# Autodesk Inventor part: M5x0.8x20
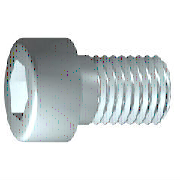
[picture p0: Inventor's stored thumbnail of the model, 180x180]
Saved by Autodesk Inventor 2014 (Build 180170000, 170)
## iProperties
IsCustomPart: 0
Created: 2009-02
Part Number: M5x0.8x20
Material: Steel, Mild
Description: 6각머리 태핑 나사
Document SubType Name: Modeling
Standard: KS B 1003
Designer: KYOUNG IL JANG
Standards Organization: KS
Language: ko-KR
Size Designation: M 5 x 20
Categories: <MemberInstance><Categories><Category DisplayName="조임쇠" InternalName="e4da775c-781d-43d5-af7c-5136215cf5a6" Mnemonic="FSTN"><Category DisplayName="볼트" InternalN
Density: 7.86 g/cm^3
Appearance: Metal-Steel
Mass: 4.9629 g
Surface Area: 5.88237 cm^2
Volume: 0.631412 cm^3
Author: KYOUNG IL JANG
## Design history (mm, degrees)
sketch "스케치1"
  geometry: L1 (-1.167, 0)-(20, 0); L2 (20, 0)-(20, 2.5); L3 (20, 2.5)-(2, 2.5); L4 (2, 2.5)-(1.509, 2.5); L5 (1.509, 2.5)-(0, 2.5); L6 (0, 2.5)-(0, 4.25); L7 (0, 4.25)-(-5, 4.25); L8 (-5, 4.25)-(-5, 2.309); L9 (-5, 2.309)-(-2.5, 2.309); L10 (-2.5, 2.309)-(-1.167, 0); L11 (-10, 0)-(25, 0) reference; L12 (0, -0.85)-(0, 5.1) reference; L13 (2, 2.5)-(0, 2.5)
  constraints: 22 end point, 6 parallel, 2 collinear, 2 perpendicular, 1 horizontal, 1 point on line
  dimensions: "d1" = 18 distance from line of L3.end L2 (= GEL); "d2" = 0.49086 distance of L4.end L3.end (computed from GAL); "d3" = 5 distance between parallel lines of L8 L6 (= KOH); "d4" = 2.5 distance of L8.end L9.end (= INTI); "d5" = 60 deg angle of L10 L1; "d6" = 5 diameter of L3 L1 (= GD); "d7" = 5 diameter of L5 L1 (= BDM); "d8" = 4.6188 diameter of L9 L1 (= 1.1547 x SW); "d9" = 8.5 diameter of L7 L1 (= KOD); "d26" = 20 distance between parallel lines of L12 L2 (= NLG)
revolve "본체" sketch "스케치1" stored, may be unused: angle "d10" = 90 deg
sketch "스케치2"
  geometry: L1 (0, -5.95)-(0, 5.95) reference; L2 (-5.95, 0)-(5.95, 0) reference; L3 (2.309, 0)-(1.155, -2); L4 (1.155, -2)-(-1.155, -2); L5 (-1.155, -2)-(-2.309, 0); L6 (-2.309, 0)-(-1.155, 2); L7 (-1.155, 2)-(1.155, 2); L8 (1.155, 2)-(2.309, 0); 2 further points
  constraints: 12 end point, 1 coincident, 1 horizontal alignment, 1 point on line, 12 other
extrude "슬롯" join sketch "스케치2" stored distance "d11" = 10; taper "d12" = 0 deg
workplane "Work Plane1"
fillet "Fillet2" dims "d30" = 0.1 (= R)
body "Solid1"
fillet "모깎기1" dims "d17" = 0.5 (= RR)
feature "스레드" dims "d13" = 18 (= GEL), "d14" = 0
chamfer "모따기1" distance "d15" = 0.49076 (= -0.5 x SPD + 0.5 x GD); stored, may be unused: second distance "d16" = 0.49076 (= GUL), angle "d27" = 45 deg
other parameters: "GD" = 5 (= NND) [user parameter; used in 2 equation terms], "NLG" = 20 [user parameter; used in 1 equation term], "GEL" = 18 [user parameter; used in 2 equation terms], "KOD" = 8.5 [user parameter; used in 1 equation term], "KOH" = 5 [user parameter; used in 1 equation term], "INTI" = 2.5 [user parameter; used in 1 equation term], "GAL" = 0.49076 (= 0.61345 x PTC) [user parameter; used in 1 equation term], "GUL" = 0.49076 (= 0.61345 x PTC) [user parameter; used in 1 equation term], "BDM" = 5 (= NND) [user parameter; used in 1 equation term], "SW" = 4 [user parameter; used in 2 equation terms], "RR" = 0.5 [user parameter; used in 1 equation term], "SPD" = 4.01848 (= NND - 1.2269 x PTC) [user parameter; used in 1 equation term], "d19" = 0, "d28" = 0, "d29" = 0, "R" = 0.1 [user parameter; used in 1 equation term], "PHH" = 0.2 [user parameter], "GD1" = 4.01848 (= THREADDIA - 1.2269 x PTC) [user parameter], "THREADDIA" = 5 [user parameter; used in 1 equation term], "FAWI" = 45 deg [user parameter], "TPU" = 12.5 (computed from PTC) [user parameter], "PTC" = 0.8 [user parameter; used in 5 equation terms], "NND" = 5 [user parameter; used in 3 equation terms], "TOA" = 30 deg [user parameter], "E0" = 4.62 (= 1.155 x SW) [user parameter]
